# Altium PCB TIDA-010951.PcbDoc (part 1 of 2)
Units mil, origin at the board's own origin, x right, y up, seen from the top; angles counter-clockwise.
Board outline 3346.46 x 3346.46 mil, 2 copper layers (Top Layer, Bottom Layer), stack 62 mil thick; 118 components, 74 nets, 305 pads, 166 vias.
Unrouted connection lines stored in the file: 4.
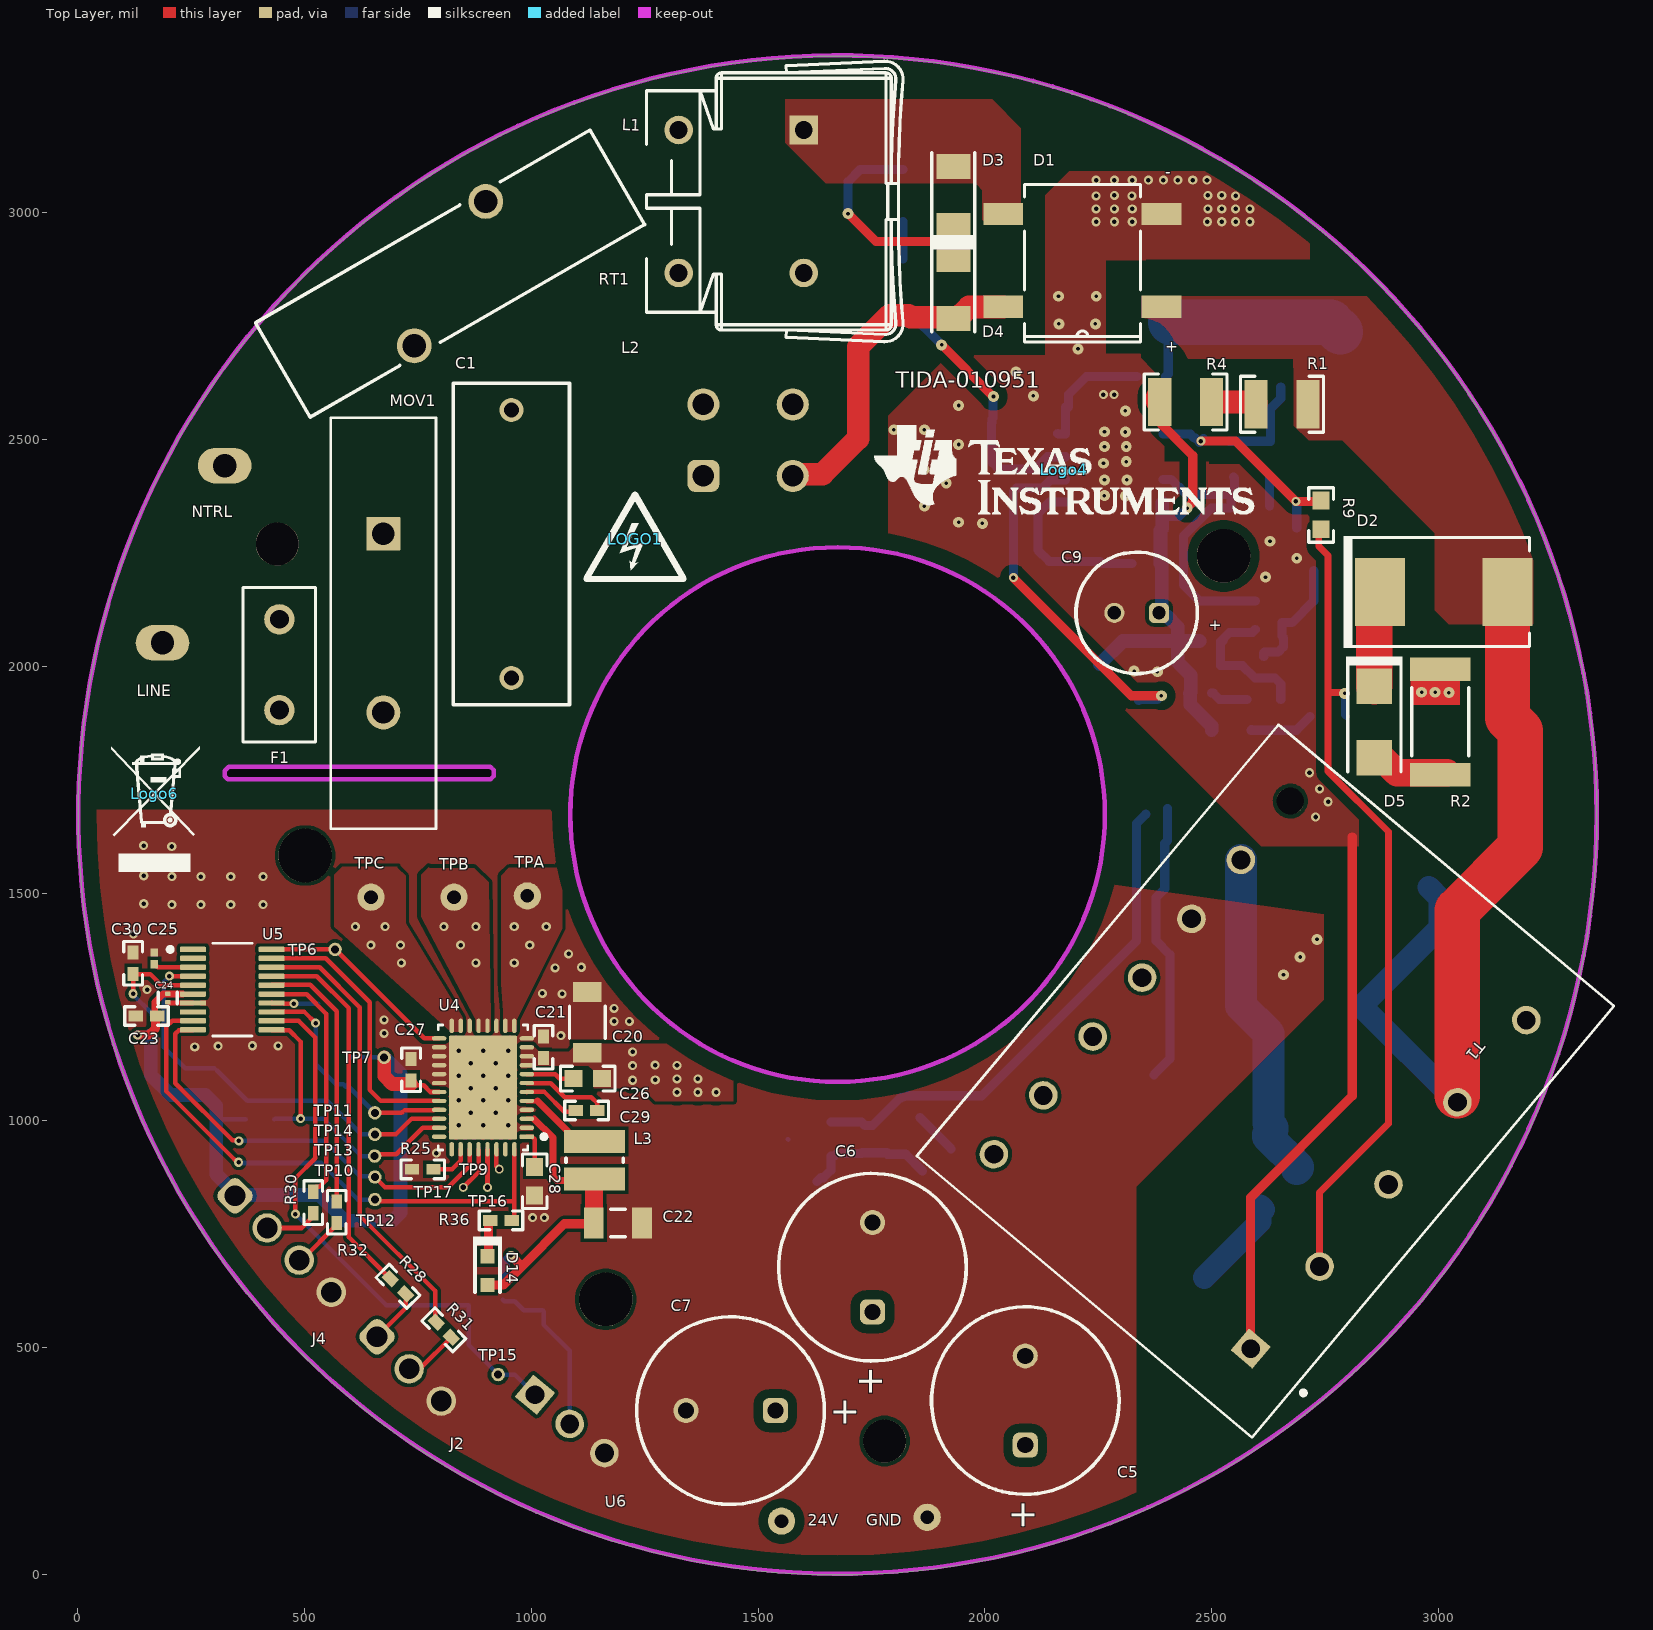
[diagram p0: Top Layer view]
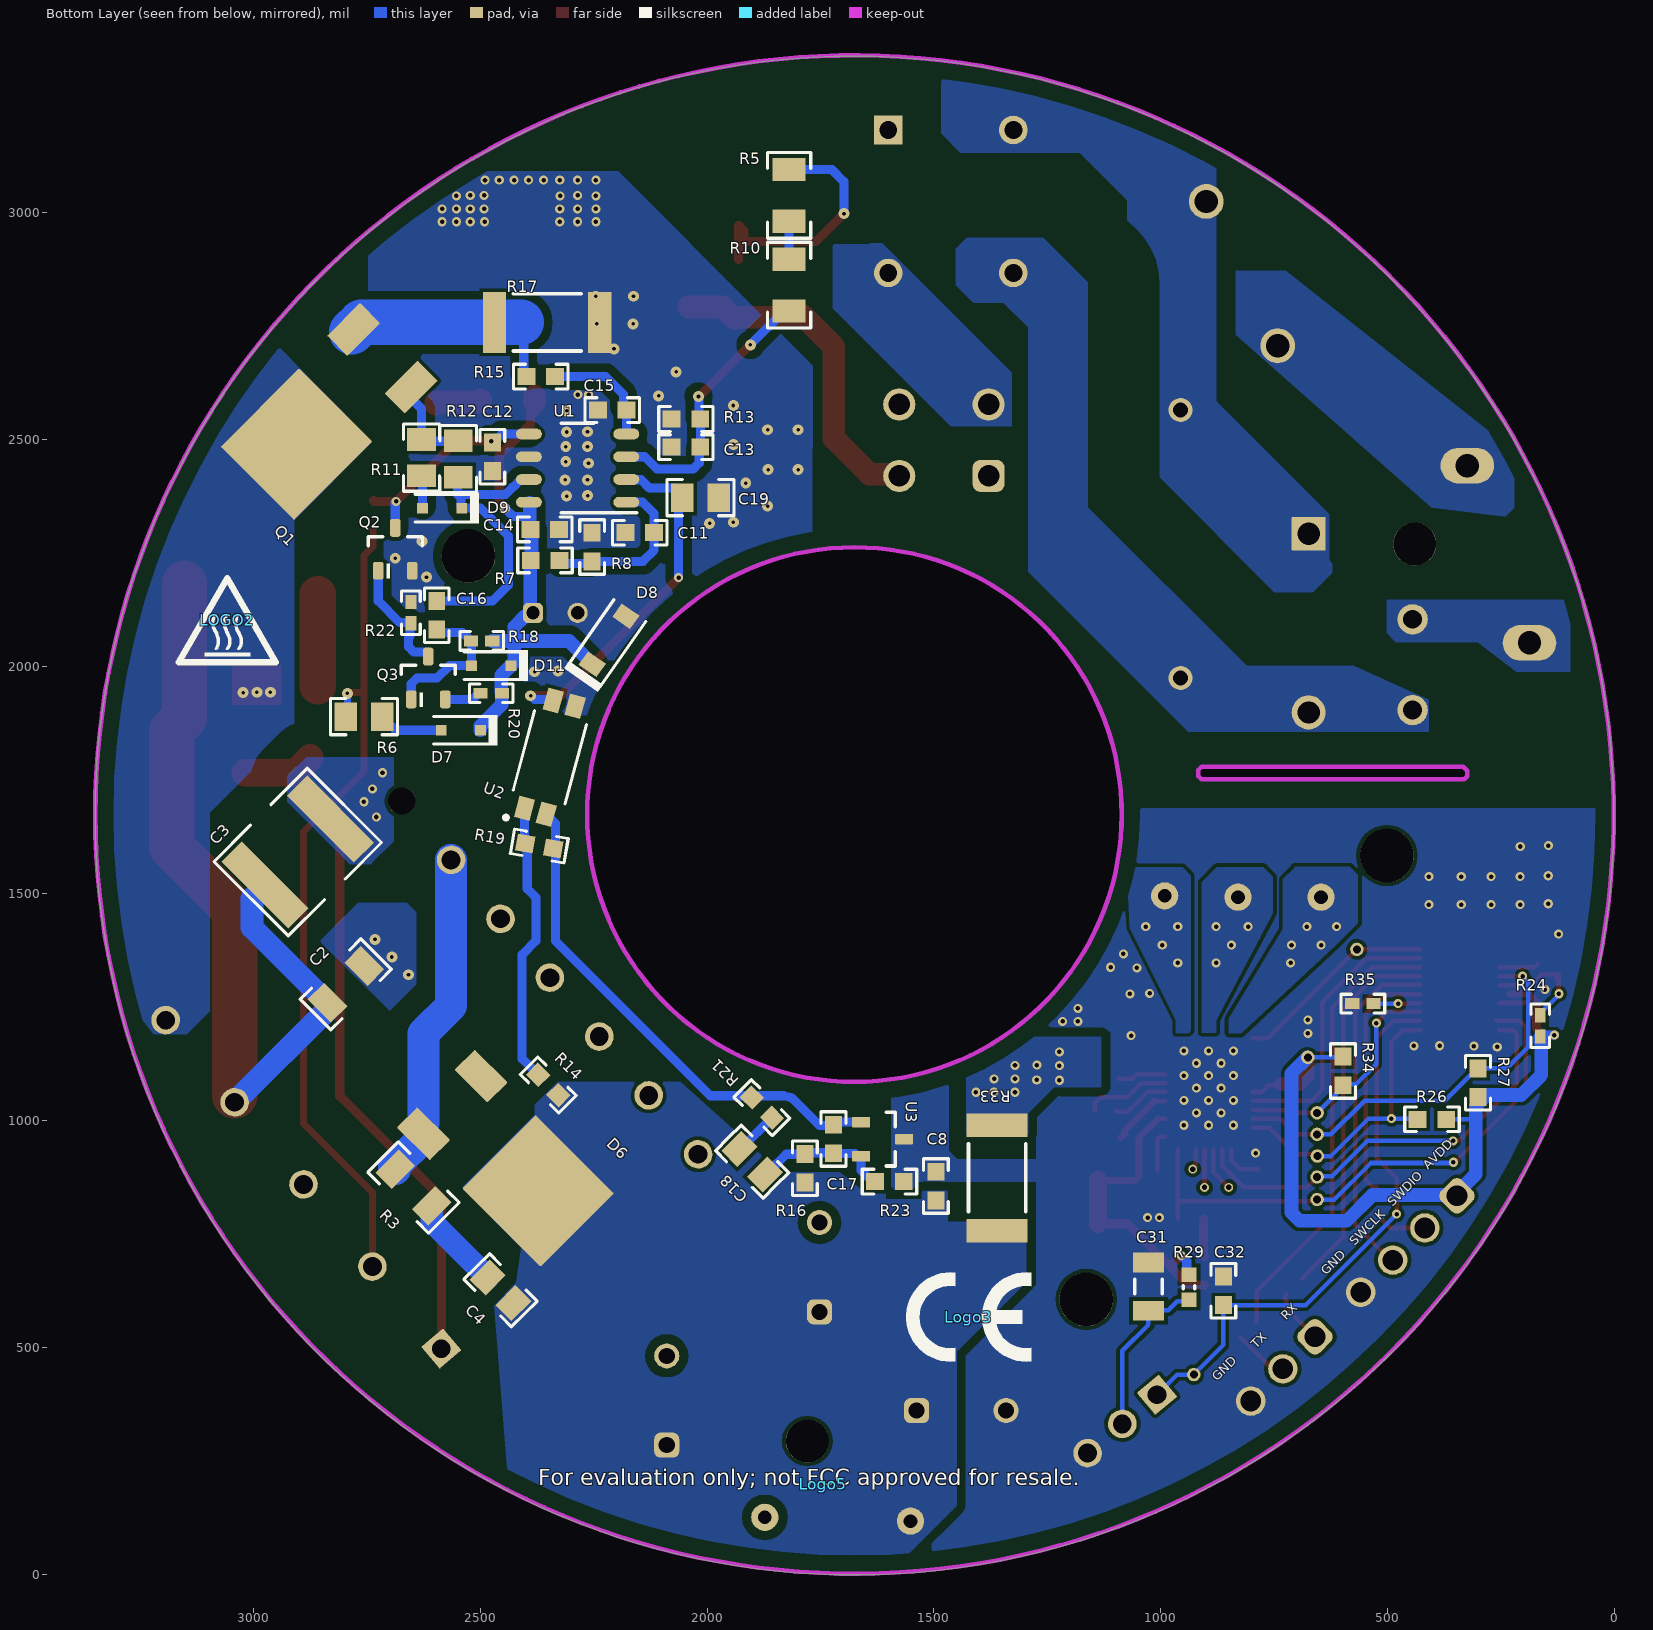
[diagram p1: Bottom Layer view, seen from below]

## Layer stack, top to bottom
Top Solder: solder mask 0.4, Solder Resist, Dk 3.5
Top Layer: signal copper 1.4
Dielectric1: core 59.2, FR-4 High Tg, Dk 4.8
Bottom Layer: signal copper 1.4
Bottom Solder: solder mask 0.4, Solder Resist, Dk 3.5

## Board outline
1675.2,-1.2 cw(c1675.2,1672.03) 1.97,1672.03 cw(c1675.2,1672.03) 1675.2,3345.26 cw(c1675.2,1672.03) 3348.42,1672.03 cw(c1675.2,1672.03)
cut-out: 1675.2,1085.28 cw(c1675.2,1674.21) 1086.26,1674.21 cw(c1675.2,1674.21) 1675.2,2263.15 cw(c1675.2,1674.21) 2264.13,1674.21 cw(c1675.2,1674.21)
cut-out: 333.85,1779.53 910.16,1779.53 917.32,1772.36 917.32,1758.86 910.61,1752.14 331.69,1752.14 324.98,1758.86 324.98,1770.66

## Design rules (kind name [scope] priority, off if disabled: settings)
AcuteAngle [All] p1: minimum=4.50000000000000E+0001 checktracksonly=FALSE
AssemblyTestPointUsage [All] p1: valid=2
BoardOutlineClearance BoardOutlineClearance_MountingHoles [OnCopper and InComponentClass('Mounting Holes')] p1: gap=39.37 ignorepadtopadclearanceinfootprint=FALSE
BoardOutlineClearance BoardOutlineClearance_Poly [OnCopper and IsPoly] p2: gap=25 ignorepadtopadclearanceinfootprint=FALSE
BoardOutlineClearance [OnCopper and Not InComponentClass('Logo') and not InComponentClass('FiducialMark') and not InRegion(1000,500,4000,800) and not InPoly] p3: gap=40 ignorepadtopadclearanceinfootprint=FALSE
Clearance "Clearance_HV AC to PGND" [InNetClass('High Volt AC')or InNetClass('High Volt AC/2') vs InNet('PGND')] p1: gap=10 ignorepadtopadclearanceinfootprint=TRUE
Clearance Clearance_Outline [InPolygon vs OnLayer('Keep-Out Layer')] p2: gap=35.43 ignorepadtopadclearanceinfootprint=TRUE
Clearance "Clearance_HV to All" [InNetClass('High Volt DC')Or InNet('NetQ1_2') vs (InNet('PGND')) And Not InComponent('T1')And Not InComponent('R1')] p3: gap=78.74 ignorepadtopadclearanceinfootprint=TRUE
Clearance "Clearance_HV to LV" [InNetClass('High Volt DC') vs InNetClass('LV')] p4: gap=196.85 ignorepadtopadclearanceinfootprint=TRUE
Clearance "Clearance_HV to To PGND" [InNet('NetC2_2')and not InAnyComponent vs InNet('PGND')] p5: gap=118.11 ignorepadtopadclearanceinfootprint=TRUE
Clearance "Clearance_24V to GND" [InNet('+24V') or ((InNet('NetC20_1')and Not OnTopLayer)or(InNet('NetC4_1'))or (InNet('NetD6_3'))and OnBottomLayer)and Not InAnyComponent vs InNet('GND')] p6: gap=19.68 ignorepadtopadclearanceinfootprint=TRUE
Clearance "Clearance_All to PGND" [Not InAnyComponent vs InNet('PGND')] p7: gap=19.68 ignorepadtopadclearanceinfootprint=TRUE
Clearance "Clearance_High Current to PGND" [InNetClass('Primary Out') or InNet('NetQ1_3')and not InAnyComponent vs InNet('PGND')] p8: gap=118.11 ignorepadtopadclearanceinfootprint=TRUE
Clearance "Clearance_AC L to N" [(InNetClass('High Volt AC L'))And(Not InComponent('D1')) vs (InNetClass('High Volt AC N'))And(Not InComponent('D1'))] p9: gap=157.48 ignorepadtopadclearanceinfootprint=TRUE
Clearance "Clearance_TH Pin to SMD Pad" [IsThruPin And OnMultiLayer And InAnyComponent And Not( InComponent('D6')or InComponent('T1') or InComponent('C9')or InComponent('TP7')) vs InSMTComponent And OnBottomLayer] p10: gap=78.74 ignorepadtopadclearanceinfootprint=FALSE
Clearance Clearance_Keepouts [((IsTrack Or IsArc) And Not InPoly) And IsFree and IsKeepOut vs ((IsTrack Or IsArc) And Not InPoly) And IsFree and IsKeepOut] p11: gap=39.37 ignorepadtopadclearanceinfootprint=FALSE
Clearance Clearance_Poly [InPolygon and not InAnyComponent] p12: gap=8 ignorepadtopadclearanceinfootprint=TRUE
Clearance Clearance_FiducialMark [IsKeepOut and InComponentClass('FiducialMark') vs IsPad and InComponentClass('FiducialMark')] p13: gap=0 ignorepadtopadclearanceinfootprint=FALSE
Clearance [All] p14 off: gap=8 ignorepadtopadclearanceinfootprint=TRUE
ComponentClearance ComponentClearance_MountingHoles_FiducialMarks [InComponentClass('Mounting Holes') vs InComponentClass('FiducialMark')] p1 off: gap=50 collisioncheckmode=3 verticalgap=10 showdistances=FALSE
ComponentClearance ComponentClearance_Shunt [InComponentClass('Header') vs InComponentClass('Shunt')] p2 off: gap=0 collisioncheckmode=3 verticalgap=0 showdistances=FALSE
ComponentClearance ComponentClearance_Logo [InComponentClass('Logo')] p3 off: gap=30 collisioncheckmode=3 verticalgap=10 showdistances=FALSE
ComponentClearance ComponentClearance_ScrewToNut [(HasFootprint('NY PMS 440 0025 PH')) vs (HasFootprint('Keystone_1902C'))] p4 off: gap=5 collisioncheckmode=3 verticalgap=10 showdistances=FALSE
ComponentClearance ComponentClearance_MountingHoles [InComponentClass('Mounting Holes')] p5 off: gap=100 collisioncheckmode=3 verticalgap=100000 showdistances=FALSE
ComponentClearance ComponentClearance_SmallPassives [HasFootprint('0201*') or HasFootprint('0402*') or HasFootprint('0508') or HasFootprint('0603*') or HasFootprint('0612') or HasFootprint('0805*') or HasFootprint('0815*') or HasFootprint('0830*') or HasFootprint('1206*') or HasFootprint('1210*') or HasFootprint('1808*') or HasFootprint('1812*') or HasFootprint('1825*') or HasFootprint('2010*') or HasFootprint('2220*') or HasFootprint('2225*') or HasFootprint('2512*') or HasFootprint('2728*') or HasFootprint('3518*') vs HasFootprint('0201*') or HasFootprint('0402*') or HasFootprint('0508') or HasFootprint('0603*') or HasFootprint('0612') or HasFootprint('0805*') or HasFootprint('0815*') or HasFootprint('0830*') or HasFootprint('1206*') or HasFootprint('1210*') or HasFootprint('1808*') or HasFootprint('1812*') or HasFootprint('1825*') or HasFootprint('2010*') or HasFootprint('2220*') or HasFootprint('2225*') or HasFootprint('2512*') or HasFootprint('2728*') or HasFootprint('3518*')] p6 off: gap=14.96 collisioncheckmode=3 verticalgap=10 showdistances=FALSE
ComponentClearance ComponentClearance_THtoSMT [IsThruComponent vs IsSMTComponent] p7 off: gap=10 collisioncheckmode=3 verticalgap=10 showdistances=FALSE
ComponentClearance ComponentClearance_THtoTH [IsThruComponent vs IsThruComponent] p8 off: gap=10 collisioncheckmode=3 verticalgap=10 showdistances=FALSE
ComponentClearance [All] p9 off: gap=10 collisioncheckmode=3 verticalgap=10 showdistances=FALSE
DiffPairsRouting [All] p1: maxlimit=100 minlimit=10 mostfreqgap=10 toplayer_minwidth=15 toplayer_maxwidth=15 toplayer_prefwidth=15 bottomlayer_minwidth=15 bottomlayer_maxwidth=15 bottomlayer_prefwidth=15 maxuncoupledlength=1000
FabricationTestPointUsage TestPointUsage [All] p1: valid=2 allowmultiple=FALSE
FabricationTestpoint Testpoint [All] p1: side=3 testpointundercomponent=TRUE minsize=40 maxsize=100 preferedsize=60 minholesize=0 maxholesize=40 preferedholesize=32 testpointgrid=1 allowsidetop=TRUE allowsidebottom=TRUE usegrid=TRUE gridtolerance=0.01
FanoutControl Fanout_LCC [IsLCC] p1: bgadir=Out bgaviamode=Centered fanoutstyle=Auto fanoutdirection=Alternating viagrid=1 // Fanout_LCC (Default Rule)
FanoutControl Fanout_BGA [IsBGA] p2: bgadir=Out bgaviamode=Centered fanoutstyle=Auto fanoutdirection=Alternating viagrid=1 // Fanout_BGA (Default Rule)
FanoutControl Fanout_Default [All] p4: bgadir=Out bgaviamode=Centered fanoutstyle=Auto fanoutdirection=Alternating viagrid=1 // Fanout_Default (Default Rule)
FanoutControl Fanout_Small [(CompPinCount < 5)] p5: bgadir=Out bgaviamode=Centered fanoutstyle=Auto fanoutdirection=OutThenIn viagrid=1 // Fanout_Small (Default Rule)
HoleSize [All] p1: absolutevalues=TRUE maxlimit=251 minlimit=7.87 maxpercent=80.000 minpercent=20.000
MinimumSolderMaskSliver MinimumSolderMaskSliver_Logo [InComponentClass('Logo') vs InComponentClass('Logo')] p1: minsoldermaskwidth=0.7
MinimumSolderMaskSliver [All] p2: minsoldermaskwidth=3.94
PlaneConnect [All] p1: planeconnectstyle=Relief reliefexpansion=10 reliefentries=4 reliefconductorwidth=10 reliefairgap=10
PolygonConnect [All] p1: connectstyle=Direct reliefconductorwidth=10 reliefentries=4 polygonreliefangle="90 Angle" airgapwidth=10
RoutingVias ThermalPadVias [IsVia and InAnyComponent] p1: holewidth=7.87 width=19.68 viastyle="Through Hole" minholewidth=7.87 minwidth=19.68 maxholewidth=12.99 maxwidth=23.62
RoutingVias [All] p2: holewidth=16 width=34 viastyle="Through Hole" minholewidth=7.87 minwidth=24 maxholewidth=40 maxwidth=65
SilkToBoardRegionClearance [Not ((IsComment or IsDesignator) And (Hide <> 'False')) and not InRegion(1000,500,4000,800)] p1:
SilkToSilkClearance SilkToSilkClearance_Pb-FreeLogo [(HasFootprint('Pb-Free_Overlay_Medium') OR HasFootprint('Pb-Free_Overlay_Small')) vs (HasFootprint('Pb-Free_Overlay_Medium') OR HasFootprint('Pb-Free_Overlay_Small'))] p1 off: silktosilkclearance=0
SilkToSilkClearance [All] p2 off: silktosilkclearance=3.94
SilkToSolderMaskClearance SilkToComponentPadClearance [(IsPad or IsFill or IsRegion) and InAnycomponent] p1 off: minsilkscreentomaskgap=5 clearancetoexposedcopper=TRUE
SilkToSolderMaskClearance "Silk to Solder Mask Opening" [All] p2 off: minsilkscreentomaskgap=3.94 clearancetoexposedcopper=FALSE
SolderMaskExpansion [All] p1: expansion=1.97 istentingtop=FALSE
UnRoutedNet [All] p1: checkbadconnections=TRUE
Width [All] p1: maxlimit=100 minlimit=6 preferedwidth=10
14 further rules are at their usual default settings.

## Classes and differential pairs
component class Logo: Logo4
net class "High Volt AC": NetD3_1
net class "High Volt AC/2": NetR5_1
net class "High Current Sensing": NetQ1_3
net class "High Volt AC L": LINE NetC1_2 NetD1_3
net class "TL431 Ref": NetC17_2
net class "Primary Out": NetQ1_2
net class "Opto K": NetC17_1
net class "Opto A": NetR14_1
net class "High Volt DC": NetC2_2 NetR1_1
net class "High Volt AC N": NetC1_1 NetD1_4 NetL1_4
net class "Aux 16.5V": NetR6_2
net class "24V DC": +24V
net class "18V VDD": VDD
component class "TIDA-010951_Motor Driver": C20 C21 C22 C23 C24 C25 C26 C27 C28 C29 C30 C31 C32 D14 J2 J4 L3 LOGO1 LOGO2 Logo3 Logo4 Logo5 Logo6 R24 R25 R26 R27 R28 R29 R30 R31 R32 R33 R34 R35 R36 TP6 TP7 TP9 TP10 TP11 TP12 TP13 TP14 TP15 TP16 TP17 TPA TPB TPC U4 U5 U6
component class TIDA-010951_ACDC: 24V +24V C1 C2 C3 C4 C5 C6 C7 C8 C9 C11 C12 C13 C14 C15 C16 C17 C18 C19 D1 D2 D3 D4 D5 D6 D7 D8 D9 D11 F1 GND L1 L2 MOV1 Q1 Q2 Q3 R1 R2 R3 R4 R5 R6 R7 R8 R9 R10 R11 R12 R13 R14 R15 R16 R17 R18 R19 R20 R21 R22 R23 RT1 T1 U1 U2 U3
component class Header: J2 J4

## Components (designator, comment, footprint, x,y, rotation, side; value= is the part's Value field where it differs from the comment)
24V "TP_H0.45P0.75" TP_H045P075#1 1551.72,117.53 r90 top
C1 "450MPK474J" MPK_1800x650 956.69,2270.28 r90 top value=0.47uF
C2 "GRM31BR73A222KW01L" 1206 2795.86,1300.23 r315 bottom value=2200pF
C3 "GRM55DR73A104KW01L" 2220 2901.74,1591.58 r135 bottom value=0.1uF
C4 "DNP" 0805_HV 2455.01,626.12 r225 bottom
C5 "1000uF" WCAP-ATLL_D10H30 2088.76,383.17 r270 top
C6 "1000uF" WCAP-ATLL_D10H30 1752.12,676.93 r270 top
C7 "1000uF" WCAP-ATLL_D10H30 1439.61,361.01 r0 top
C8 "UMK107AB7105KA-T" 0603 1495.67,855.78 r90 bottom value=1uF
C9 "UVR2A220MED1TD" VR_630X1100 2334.22,2118.53 r180 top value=22uF
C11 "C1608X7R1H103K080AA" 0603 2148.2,2295.14 r0 bottom value=0.01uF
C12 "GRM1885C1H100JA01D" 0603 2472.85,2462.57 r90 bottom value=10pF
C13 "C0603X102K5RACTU" 0603 2046.52,2483.65 r0 bottom value=1000pF
C14 "GRM188R71H104KA93D" 0603 2357.71,2302.39 r180 bottom value=0.1uF
C15 "C1608C0G1H101J080AE" 0603 2208.87,2565.24 r0 bottom value=100pF
C16 "GRM1885C1H100JA01D" 0603 2595.49,2113.6 r90 bottom value=10pF
C17 "C1608X5R1V225K080AC" 0603 1721.4,959.4 r270 bottom value=2.2uF
C18 "C2012X7R1V475K125AC" 0805_HV 1900.57,909.42 r45 bottom value=4.7uF
C19 "C2012X6S1H225K125AB" 0805_HV 2014.31,2372.54 r180 bottom value=2.2uF
C20 "UMK316BBJ106KL-T" 1206_190 1124.02,1216.4 r90 top value=10uF
C21 "C1005X7R1H104K050BB" 0402 1027.28,1161.47 r90 top value=0.1uF
C22 "GRM31CR71A226KE15L" 1206_180L 1191.31,774.39 r0 top value=22uF
C23 "GRM155R60J106ME11" 0402 152.56,1230.31 r180 top value=10uF
C24 "GRM033R60J104KE19D" FP-GRM033R60J104KE19D_0201-MFG 199.62,1269.85 r90 top
C25 "GRM033R60J474KE90D" 0201_033 170.06,1357.43 r270 top value=0.47uF
C26 "GRM188R71C105KE15D" 0603 1125,1092.52 r180 top value=1uF
C27 "GRM155R60J105KE19D" 0402 735.64,1111.89 r90 top value=1uF
C28 "LMK107BJ225KA-T" 0603 1007.97,866.38 r270 top value=2.2uF
C29 "C1005X7R1H473K050BB" 0402 1122.24,1022.16 r0 top value=0.047uF
C30 "GCM155R71H102KA37D" 0402 123.03,1346.46 r90 top value=1000pF
C31 "GRM31CR71A226KE15L" 1206_180L 1027.28,634.04 r90 bottom value=22uF
C32 "885012006012" 0603 862.2,625 r90 bottom value=470pF
D1 "DF1506S-T" DF-S 2214.79,2895.14 r180 top value=600V
D2 "SMCJ150A-TP" SMC 3010.83,2164.37 r0 top value=150V
D3 "CGRM4005-G" MINI-SMA 1930.37,3037.4 r90 top value=600V
D4 "CGRM4005-G" MINI-SMA 1930.37,2832.5 r270 top value=600V
D5 "MURA160T3G" SMA 2857.95,1878.21 r270 top value=600V
D6 "STTH802B-TR" DPAK 2466.69,939.81 r225 bottom value=200V
D7 "BAS20HT1G" SOD-323 2542.56,1860.04 r0 bottom
D8 "MMSZ4705-E3-08" SOD-123 2215.91,2058.45 r125 bottom value=18V
D9 "BAS20HT1G" SOD-323 2583.66,2349.29 r0 bottom
D11 "BAS20HT1G" SOD-323 2475.44,2002.38 r0 bottom
D14 "150060RS75000" WL-SMCW_RED 903.9,669.26 r270 top value=Red
F1 "39213150000" FUSE_392 445.41,2004.33 r90 top value=3.15A
GND "TP_H0.45P0.75" TP_H045P075#1 1872.65,125.84 r90 top
J2 "61300311121" WURTH_61300311121 731.22,452.83 r315 top
J4 "61300411121" WURTH_61300411121 453.74,727.95 r315 top
L1 "744861018" WE-TFCH_UT 1462.96,3025 r270 top value=1.8mH
L2 "7447231102" WE-TIF_1018 1477.98,2499.04 r0 top value=1mH
L3 "78438335470" WE-MAIA_3015 1139.95,912.69 r270 top value=47uH
LOGO1 "DANGER HIGH VOLTAGE" IEC_HighVoltage_Small 1228.93,2281.31 r0 top
LOGO2 "CAUTION HOT SURFACE" IEC_HotSurface_Small 3056.94,2102.44 r180 bottom
Logo3 "CE Mark" CE_Mark_5mm 1423.87,567.11 r180 bottom
Logo4 "Texas Instruments" TI_Stacked_Overlay_Small 2174.42,2433.74 r0 top
Logo5 "FCC disclaimer" FCC_disclaimer 1744.47,198.63 r180 bottom
Logo6 "WEEE logo" WEEE_Minimum 170.7,1720.42 r0 top
MOV1 "MOV-20D471K" FP-MOV-20D471K_RADIAL-MFG 674.5,2096.03 r270 top
Q1 "IPD70R360P7SAUMA1" DPAK 2809.88,2584.81 r315 bottom value=700V
Q2 "MMBT3904-7-F" SOT-23 2686.96,2258.56 r90 bottom value="40 V"
Q3 "MMBT3906-7-F" SOT-23 2614.19,1975.18 r90 bottom value="40 V"
R1 "RC1210JR-07200KL" 1210 2654.48,2578.25 r0 top value=200k
R2 "CRCW251222R0JNEGHP" 2512 3003.28,1878.21 r270 top value=22
R3 "CRCW120647R0JNEA" 1206 2646.78,852.6 r225 bottom value=47
R4 "RC1210JR-07200KL" 1210 2442.14,2583.29 r0 top value=200k
R5 "RC1206FR-07510KL" 1206 1818.98,3038.39 r90 bottom value=510k
R6 "RC0805JR-073R3L" 0805_HV 2755.86,1889.97 r0 bottom value=3.3
R7 "RC0603FR-07301KL" 0603 2356.87,2234.32 r0 bottom value=301k
R8 "RC0603FR-0730K1L" 0603 2253.26,2263.65 r270 bottom value=30.1k
R9 "RC0603FR-0747KL" 0603 2740.63,2334.35 r270 top value=47.0k
R10 "RC1206FR-07510KL" 1206 1818.98,2840.76 r90 bottom value=510k
R11 "RC0805JR-072R2L" 0805_HV 2629.09,2460.52 r90 bottom value=2.2
R12 "RPC0805JT4R70" 0805_HV 2548.03,2457.57 r90 bottom value=4.7
R13 "RC0603FR-076K8L" 0603 2046.52,2545.66 r180 bottom value=6.80k
R14 "CR0603-JW-472GLF" 0603 2349.77,1078.32 r225 bottom value=4.7k
R15 "RC0603JR-071KL" 0603 2366.58,2639.12 r180 bottom value=1.0k
R16 "RC0603FR-07412KL" 0603 1784.34,895.17 r270 bottom value=412k
R17 "ERJ-1TRQJR68U" 2512 2352.36,2758.54 r0 bottom value=0.68
R18 "ERJ-2RKF1002X" 0402 2496.52,2056.7 r0 bottom value=10.0k
R19 "RC0603JR-071KL" 0603 2369.57,1604.94 r10 bottom value=1.0k
R20 "ERJ-2GEJ203X" 0402 2475.44,1941.58 r0 bottom value=20k
R21 "RC0603FR-0718KL" 0603 1879.19,1028.57 r225 bottom value=18.0k
R22 "RC0402FR-074K99L" 0402 2652.45,2119.09 r270 bottom value=4.99k
R23 "RC0603FR-0747K5L" 0603 1598.1,865.38 r0 bottom value=47.5k
R24 "RC0402FR-0747KL" 0402 164.37,1208.66 r270 bottom value=47.0k
R25 "CRCW040210K0JNED" 0402 761.42,892.48 r180 top value=10k
R26 "RC0603FR-075K1L" 0603 402.76,1002.77 r180 bottom value=5.10k
R27 "RC0603FR-075K1L" 0603 301.42,1083.53 r270 bottom value=5.10k
R28 "CRCW0402180RJNED" 0402 706.69,634.84 r315 top value=180
R29 "CRCW06035K10JNEA" 0603L 937.99,632.87 r90 bottom value=5.1k
R30 "CRCW0402180RJNED" 0402 520.16,819.32 r270 top value=180
R31 "CRCW0402180RJNED" 0402 807.83,539.04 r315 top value=180
R32 "CRCW0402180RJNED" 0402 572.04,798.01 r270 top value=180
R33 "CRCW25120000Z0EGHP" 2512 1360.87,873.49 r90 bottom value=0
R34 "RC0603FR-075K1L" 0603 598.74,1109.29 r90 bottom value=5.10k
R35 "CRCW040210K0JNED" 0402 555.01,1257.77 r0 bottom value=10k
R36 "ERA2AED102X" 0402 933.8,780 r180 top value=1.00k
RT1 "SCK205R0MSBY502" SCK20_S 821.35,2865.94 r120 top value=5
T1 "G084231" FP-G084231_PTH_TRANSFORMER_31MM50_24MM50-MFG 2617.63,1087.09 r140 top locked
TP6 "TP_H0.45P0.75" TP_H045P075#2 568.19,1377.12 r140 top
TP7 "TP_H0.45P0.75" TP_H045P075#2 676.21,1139.19 r180 top
TP9 "TP_H0.45P0.75" TP_H045P075#3 929.82,892.96 r180 top
TP10 "TP_H0.45P0.75" TP_H045P075#2 655.8,875.67 r250 top
TP11 "TP_H0.45P0.75" TP_H045P075#2 655.8,1017.06 r180 top
TP12 "TP_H0.45P0.75" TP_H045P075#2 655.8,826.04 r180 top
TP13 "TP_H0.45P0.75" TP_H045P075#2 655.32,921.81 r180 top
TP14 "TP_H0.45P0.75" TP_H045P075#2 655.8,969.55 r180 top
TP15 "TP_H0.45P0.75" TP_H045P075#2 927.54,440.4 r270 top
TP16 "TP_H0.45P0.75" TP_H045P075#3 903.94,852.73 r45 top
TP17 "TP_H0.45P0.75" TP_H045P075#3 850.61,852.73 r45 top
TPA "TP_H0.45P0.75" TP_H045P075#1 991.77,1495.06 r90 top
TPB "TP_H0.45P0.75" TP_H045P075#1 830.14,1492.22 r90 top
TPC "TP_H0.45P0.75" TP_H045P075#1 647.19,1492.22 r90 top
U1 "UCC28810DR" D0008A_N 2285.14,2437.57 r0 bottom
U2 "VOS617A-7X001T" SSOP-4_VISHAY 2346.48,1800.19 r105 bottom
U3 "ATL431AIDBZR" DBZ0003A_N 1613.16,958.99 r180 bottom
U4 "MCF8315A1VRGFR" RGF0040E-IPC_B 894.06,1072.77 r180 top
U5 "MSPM0L1306SDGS20" DGS0020A-MFG 341.65,1288.53 r0 top
U6 "TSOP32238" FP-TSOP32238_SIP3-MFG 1053.36,293.94 r230 top

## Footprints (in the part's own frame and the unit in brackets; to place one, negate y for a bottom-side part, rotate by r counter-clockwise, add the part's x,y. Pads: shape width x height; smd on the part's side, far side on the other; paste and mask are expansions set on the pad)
0201_033 [mm] "SMD, 2-Leads, Height 0.33mm"
  rect 0.46x0.42 smd mask+0.048: 1(-0.33,0) 2(0.33,0)
  body extent -0.31,-0.16 0.31,0.16, height 0.33
0402 [mm] "0402 from SM-752 data"
  rect 0.8x0.6 smd: 1(-0.6,0) 2(0.6,0)
  silkscreen extent -1.22,-0.52 1.22,0.52, body extent -0.55,-0.3 0.55,0.3, height 0.6
0603 [mm] "0603 from SM-752 data"
  rect 1x0.95 smd: 1(-0.8,0) 2(0.8,0)
  silkscreen extent -1.52,-0.69 1.52,0.69, body extent -0.87,-0.47 0.87,0.47, height 1
0603L [mm] "0603 from SM-752 data"
  rect 0.8x0.85 smd: 1(-0.7,0) 2(0.7,0)
  silkscreen extent -0.07,-0.33 0.07,0.33, body extent -0.87,-0.47 0.87,0.47, height 1
0805_HV [mil] "0805 with 30mil clearance between pads"
  rect 50x63 smd: 1(-40,0) 2(40,0)
  silkscreen extent -74,-40 74,40, body extent -43,-29 43,29, height 57
1206 [mm] "1206 from SM-752 data"
  rect 1.3x1.85 smd: 1(-1.45,0) 2(1.45,0)
  silkscreen extent -2.4,-1.21 2.4,1.21, body extent -1.7,-0.9 1.7,0.9, height 1.35
1206_180L [mm] "1206_180"
  rect 1.1x1.75 smd: 1(-1.35,0) 2(1.35,0)
  silkscreen extent -0.4,-0.77 0.4,0.77, body extent -1.75,-0.95 1.75,0.95, height 1.8
1206_190 [mm] "1206_190"
  rect 1.1x1.6 smd: 1(-1.7,0) 2(1.7,0)
  silkscreen extent -0.9,-1 0.9,1, body extent -1.75,-0.95 1.75,0.95, height 1.9
1210 [mm] "1210 from SM-752 data"
  rect 1.3x2.7 smd: 1(-1.45,0) 2(1.45,0)
  silkscreen extent -2.32,-1.57 2.32,1.57, body extent -1.7,-1.35 1.7,1.35, height 1.35
2220 [mm] "Chip Capacitor, Body 5.7x5.0mm, IPC Medium Density"
  rect 1.6x5.3 smd: 1(-2.6,0) 2(2.6,0)
  silkscreen extent -3.69,-2.94 3.69,2.94, body extent -2.95,-2.62 2.95,2.62, height 1.35
2512 [mm] "Chip Resistor, Body 6.3x3.2mm, IPC Medium Density"
  rect 1.3x3.4 smd: 1(-2.95,0) 2(2.95,0)
  silkscreen extent -1.9,-1.6 1.9,1.6, body extent -3.22,-1.67 3.22,1.67, height 0.71
CE_Mark_5mm [mil] "Minimum text height for CE Mark"
  silkscreen extent -138,-98 138,98
D0008A_N [mm] "SOIC, 8-Leads, Body 4.9x3.9mm, Pitch 1.27mm, IPC Medium Density"
  oval 1.45x0.6 smd: 1(-2.725,1.905) 2(-2.725,0.635) 3(-2.725,-0.635) 4(-2.725,-1.905) 5(2.725,-1.905) 6(2.725,-0.635) 7(2.725,0.635) 8(2.725,1.905)
  silkscreen extent -3.3,-2.5 0.9,2.5, body extent -3,-2.45 3,2.45, height 1.63
DBZ0003A_N [mm] "SOT23, 3-Leads, Body 2.9x1.3mm, Pitch 0.95mm, Lead Span 2.4mm, IPC Medium Density"
  rrect17% 1x0.6 smd: 1(-1.2,0.95) 2(-1.2,-0.95) 3(1.2,0)
  silkscreen extent 0.2,-1.5 0.7,1.5, body extent -1.26,-1.46 1.26,1.46, height 0.98
DF-S [mil] "Diodes Inc. recommended land pattern per ap02001.pdf rev 30"
  rect 88x49 smd: 1(-174.5,102.36) 2(-174.5,-102.36) 3(174.5,-102.36) 4(174.5,102.36)
  silkscreen extent -128,-168 128,180, body extent -205,-168 205,168, height 108
DGS0020A-MFG [mm]
  rrect33% 1.45x0.3 smd paste+0 mask+0: 1(-2.2,2.25) 2(-2.2,1.75) 3(-2.2,1.25) 4(-2.2,0.75) 5(-2.2,0.25) 6(-2.2,-0.25) 7(-2.2,-0.75) 8(-2.2,-1.25) 9(-2.2,-1.75) 10(-2.2,-2.25) 11(2.2,-2.25) 12(2.2,-1.75) 13(2.2,-1.25) 14(2.2,-0.75) 15(2.2,-0.25) 16(2.2,0.25) 17(2.2,0.75) 18(2.2,1.25) 19(2.2,1.75) 20(2.2,2.25)
  silkscreen extent -3.6,-2.6 1.1,2.6, body extent -2.45,-2.55 2.45,2.55, height 1.1
DPAK [mm] "D-PAK, 3-Pads, Body 6.22x6.73mm (max), TO-252AA using nominal STEP model"
  rrect6% 2.6x1.6 smd: 1(-3.4,2.28) 3(-3.4,-2.28)
  rrect2% 6.2x5.8 smd paste-3: 2(3.4,0)
  body extent -3.86,-3.29 5.84,3.29, height 2.48
FCC_disclaimer [mil]
FP-G084231_PTH_TRANSFORMER_31MM50_24MM50-MFG [mm]
  rrect6% 1.6x1.6 hole 1.05 paste-1000 mask+0: 1(-9,12)
  round 1.6 hole 1.05 paste-1000 mask+0: 2(-9,6) 3(-9,0) 4(-9,-6) 5(-9,-12) 7(9,-8.6) 8(9,-4.3) 9(9,0) 10(9,4.3) 11(9,8.6) 12(9,12.9)
  oval 1.524x1.27 hole 1.524 paste-1000 mask+0: 6(9,-12.9)
  silkscreen extent -12.97,-15.75 12.25,15.75, body extent -12.35,-15.85 12.35,15.85, height 0.25
FP-GRM033R60J104KE19D_0201-MFG [mm]
  rrect40% 0.25x0.3 smd paste+0 mask+0: 1(-0.238,0) 2(0.238,0)
  silkscreen extent -0.31,-0.53 0.32,0.53, body extent -0.3,-0.15 0.3,0.15, height 0.33
FP-MOV-20D471K_RADIAL-MFG [mm]
  rrect5% 1.9x1.9 hole 1.25 paste-1000 mask+0: 1(-5,0)
  round 1.9 hole 1.25 paste-1000 mask+0: 2(5,0)
  silkscreen extent -11.5,-2.95 11.5,2.95, body extent -11.6,-3.05 11.6,3.05, height 0.25
FP-TSOP32238_SIP3-MFG [mm]
  rrect6% 1.6x1.6 hole 1.05 paste-1000 mask+0: 1(-1.25,-2.54)
  round 1.6 hole 1.05 paste-1000 mask+0: 2(-1.25,0) 3(-1.25,2.54)
  body extent -3,-3.44 3,3.44, height 0.25
FUSE_392 [mm] "LITTELFUSE"
  round 1.7 hole 1.05: 1(-2.54,0) 2(2.54,0)
  silkscreen extent -4.32,-2.03 4.32,2.03, body extent -4.25,-2 4.25,2, height 8
IEC_HighVoltage_Small [mil]
  silkscreen extent -107,-88 107,97
IEC_HotSurface_Small [mil]
  silkscreen extent -107,-93 107,92
MINI-SMA [mm] "COMCHIP"
  rect 1.4x1.9 smd: 1(-1.65,0) 2(1.65,0)
  silkscreen extent -3,-1.3 2.4,1.3, body extent -1.95,-0.9 1.95,0.9, height 1.7
MPK_1800x650 [mm] "TH, 2-Leads, Body 18x6.5mm, Lead Spacing 15mm"
  round 1.35 hole 0.85: 1(-7.5,0) 2(7.5,0)
  silkscreen extent -9,-3.25 9,3.25, body extent -9,-3.25 9,3.25, height 12
RGF0040E-IPC_B [mm]
  rrect41% 0.806x0.242 smd paste+0 mask+0: 1(-2.453,2.75)
  rrect100% 0.806x0.242 smd paste+0 mask+0: 2(-2.453,2.25) 3(-2.453,1.75) 4(-2.453,1.25) 5(-2.453,0.75) 6(-2.453,0.25) 7(-2.453,-0.25) 8(-2.453,-0.75) 9(-2.453,-1.25) 10(-2.453,-1.75) 11(-2.453,-2.25) 12(-2.453,-2.75) 21(2.453,-2.75) 22(2.453,-2.25) 23(2.453,-1.75) 24(2.453,-1.25) 25(2.453,-0.75) 26(2.453,-0.25) 27(2.453,0.25) 28(2.453,0.75) 29(2.453,1.25) 30(2.453,1.75) 31(2.453,2.25) 32(2.453,2.75)
  rrect100% 0.242x0.806 smd paste+0 mask+0: 13(-1.75,-3.453) 14(-1.25,-3.453) 15(-0.75,-3.453) 16(-0.25,-3.453) 17(0.25,-3.453) 18(0.75,-3.453) 19(1.25,-3.453) 20(1.75,-3.453) 33(1.75,3.453) 34(1.25,3.453) 35(0.75,3.453) 36(0.25,3.453) 37(-0.25,3.453) 38(-0.75,3.453) 39(-1.25,3.453) 40(-1.75,3.453)
  rrect3% 3.8x5.8 smd paste-1000 mask+0: 41(0,0)
  silkscreen extent -3.53,-3.5 2.5,3.5, body extent -2.5,-3.5 2.5,3.5, height 1
SCK20_S [mm] "TH, 2-Leads, Dia 20mm, Pin Spacing 7.5mm"
  round 1.95 hole 1.3: 1(-2.5,3.75) 2(2.5,-3.75)
  silkscreen extent -3.06,-10.8 3.06,10.8, body extent -3,-10.75 3,10.75, height 24.5
SMA [mm] "Molded Diode, 2-Leads, Body 4.3x2.6mm, IPC Medium Density, based on OnSemi component dimensions and land pattern"
  rect 2x2 smd: 1(-2,0) 2(2,0)
  silkscreen extent -3.66,-1.57 2.79,1.57, body extent -2.6,-1.3 2.6,1.3, height 2.42
SMC [mil] "Molded Diode, 2-Leads, Body 6.9x5.8mm, IPC Medium Density, based on OnSemi component dimensions and land patterns"
  rect 110x150 smd: 1(-140.49,0) 2(140.49,0)
  silkscreen extent -221,-123 189,124, body extent -156,-116 156,116, height 91
SOD-123 [mm] "On Semi recommended land pattern"
  rect 0.915x1.22 smd: 1(-1.638,0) 2(1.637,0)
  silkscreen extent -2.74,-1.17 2.03,1.17, body extent -1.93,-0.9 1.93,0.9, height 1.35
SOD-323 [mm] "NXP recommended land pattern"
  rect 0.6x0.6 smd paste-0.05: 1(-1.1,0) 2(1.1,0)
  silkscreen extent -2.06,-0.86 1.53,0.86, body extent -1.3,-0.67 1.3,0.68, height 1.1
SOT-23 [mm] "SOT23, 3-Leads, Body 2.9x1.3mm, Pitch 0.95mm, Lead Span 2.5mm, IPC Medium Density"
  rrect50% 1x0.6 smd: 1(-1.2,0.95) 2(-1.2,-0.95) 3(1.2,0)
  silkscreen extent -1.63,-1.5 0.7,1.5, body extent -1.16,-1.45 1.21,1.45, height 1
SSOP-4_VISHAY [mm] "Vishay Recommened"
  rect 1.25x0.9 smd: 1(-3.125,0.635) 2(-3.125,-0.635) 3(3.125,-0.635) 4(3.125,0.635)
  silkscreen extent -3.98,-1.5 2.3,1.59, body extent -3.5,-1.45 3.5,1.45, height 2.42
TI_Stacked_Overlay_Small [mil]
  silkscreen extent -418,-98 418,98
TP_H045P075#1 [mil] "TP_H0.45P0.75"
  round 60 hole 30: 1(0,0)
TP_H045P075#2 [mil] "TP_H0.45P0.75"
  round 29.53 hole 17.72: 1(0,0)
TP_H045P075#3 [mil] "TP_H0.45P0.75"
  round 19.68 hole 11.81: 1(0,0)
VR_630X1100 [mm] "TH, 2-Leads, Dia 6.3mm, Pin Spacing 2.5mm"
  rrect50% 1.125x1.125 hole 0.75: 1(-1.25,0)
  round 1.125 hole 0.75: 2(1.25,0)
  silkscreen extent -3.4,-3.4 3.4,3.4, body extent -3.4,-3.4 3.41,3.4, height 12.51
WCAP-ATLL_D10H30 [mm] "Aluminum Electrolytic Capacitors, 10x30mm"
  rrect50% 1.4x1.4 hole 0.9: 1(2.5,0)
  round 1.4 hole 0.9: 2(-2.5,0)
  silkscreen extent -5.25,-5.25 5.25,5.25, body extent -4.99,-5 5,5, height 30.31
WE-MAIA_3015 [mm] "SMD, 2-Leads, Body 3x3mm"
  rect 1.3x3.4 smd: 1(-1.05,0) 2(1.05,0)
  silkscreen extent -0.1,-1.6 0.1,1.6, body extent -1.6,-1.6 1.6,1.6, height 1.5
WE-TFCH_UT [mm] "Wurth"
  rect 1.6x1.6 hole 1: 1(-4,3.499)
  round 1.6 hole 1: 2(-4,-3.501) 3(4,-3.501) 4(4,3.499)
  silkscreen extent -7.85,-5.3 7.85,9.05, body extent -7.85,-5.3 7.85,9.05, height 12.02
WE-TIF_1018 [mm] "TH, 4-Leads, Dia 11mm, Pitch 5mm"
  rrect50% 1.8x1.8 hole 1.2: 1(-2.5,-2)
  round 1.8 hole 1.2: 2(2.5,-2) 3(-2.5,2) 4(2.5,2)
  body extent -5.4,-5.4 5.4,5.4, height 18
WEEE_Minimum [mil] "WEEElie bin"
  silkscreen extent -95,-172 99,104
WL-SMCW_RED [mm] "WURTH"
  rect 0.8x0.8 smd: 1(-0.8,0) 2(0.8,0)
  silkscreen extent -1.9,-0.8 1.2,0.8, body extent -0.85,-0.45 0.85,0.45, height 0.8
WURTH_61300311121 [mm] "Header, 2.54mm, 3x1, TH"
  rrect50% 1.65x1.65 hole 1.15: 1(-2.54,0)
  round 1.65 hole 1.15: 2(0,0) 3(2.54,0)
  body extent -3.81,-1.27 3.81,1.27, height 8.54
WURTH_61300411121 [mm] "Header, 2.54mm, 4x1, TH"
  rrect50% 1.65x1.65 hole 1.15: 1(-3.81,0)
  round 1.65 hole 1.15: 2(-1.27,0) 3(1.27,0) 4(3.81,0)
  body extent -5.08,-1.27 5.08,1.27, height 8.54

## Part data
24V GND TP6 TP7 TP9 TP10 TP11 TP12 TP13 TP14 TP15 TP16 TP17 TPA TPB TPC: library part CMP-0003719-1, "Testpoint", Manufacturer="Texas Instruments"
C1: library part CMP-0012309-3, "CAP, Film, 0.47 uF, 450 V, +/- 5%, TH", Cap_Case=18x6.5mm, Manufacturer=Rubycon, Supplier Part Number 1=1189-1824-ND, Tolerance_%=5%, Value1=Unknown, Value2=450V, ValueDisplayed=0.47uF
C2: library part CMP-0008918-2, "CAP, CERM, 2200 pF, 1000 V, +/- 10%, X7R, 1206", Cap_Case=1206, Manufacturer=MuRata, Supplier Part Number 1=490-3496-1-ND, TempCo=X7R, Tolerance_%=10%, Value1=Unknown, Value2=1000V, ValueDisplayed=2200pF
C3: library part CMP-0009470-2, "CAP, CERM, 0.1 uF, 1000 V, +/- 10%, X7R, 2220", Cap_Case=2220, Manufacturer=MuRata, Supplier Part Number 1=490-3505-1-ND, TempCo=X7R, Tolerance_%=10%, Value1=Unknown, Value2=1000V, ValueDisplayed=0.1uF
C4: library part CMP-0008310-1, Cap_Case=0805, TempCo=X5R, Tolerance_%=10%, Value1=Unknown, Value2=250V
C5: library part CMP-03913-55434168-1, "860160575031 WCAP-ATLL Aluminum Electrolytic Capacitors 35VDC", Capacitance=1mF, Case/Package=Radial, Leakage Current=350µA, Max Operating Temperature=105°C, Min Operating Temperature=-55°C, Ripple Current=2.136A, Tolerance=20%, Voltage Rating=35V
C6 C7: library part CMP-03913-55434168-1, "860160575031 WCAP-ATLL Aluminum Electrolytic Capacitors", Capacitance=1mF, Case/Package=Radial, Leakage Current=350µA, Max Operating Temperature=105°C, Min Operating Temperature=-55°C, Ripple Current=2.136A, Tolerance=20%, Voltage Rating=35V
C8: library part CMP-0007508-5, "CAP, CERM, 1 uF, 50 V, +/- 10%, X7R, 0603", Cap_Case=0603, Manufacturer="Taiyo Yuden", Supplier Part Number 1=587-3247-1-ND, TempCo=X7R, Tolerance_%=10%, Value1=Unknown, Value2=50V, ValueDisplayed=1uF
C9: library part CMP-0860355-1, "CAP, AL, 22 µF, 100 V, +/- 20%, TH", Cap_Case=6.3x11mm, Manufacturer=Nichicon, Tolerance_%=20%, Value2=100V, ValueDisplayed=22µF
C11: library part CMP-0007043-2, "CAP, CERM, 0.01 uF, 50 V, +/- 10%, X7R, 0603", Cap_Case=0603, Manufacturer=TDK, Supplier Part Number 1=445-1311-1-ND, TempCo=X7R, Tolerance_%=10%, Value1="0.0539 ohm", Value2=50V, ValueDisplayed=0.01uF
C12: library part CMP-0007170-4, "CAP, CERM, 10 pF, 50 V, +/- 5%, C0G/NP0, 0603", Cap_Case=0603, Manufacturer=MuRata, Supplier Part Number 1=490-1403-1-ND, TempCo=C0G/NP0, Tolerance_%=5%, Value1=Unknown, Value2=50V, ValueDisplayed=100pf
C13: library part CMP-0006976-5, "CAP, CERM, 1000 pF, 50 V, +/- 10%, X7R, 0603", Cap_Case=0603, Manufacturer=Kemet, Supplier Part Number 1=399-5348-1-ND, TempCo=X7R, Tolerance_%=10%, Value1=Unknown, Value2=50V, ValueDisplayed=1000pF
C14: library part CMP-0007434-4, "CAP, CERM, 0.1 uF, 50 V, +/- 10%, X7R, 0603", Cap_Case=0603, Manufacturer=MuRata, Supplier Part Number 1=490-1519-1-ND, TempCo=X7R, Tolerance_%=10%, Value1=Unknown, Value2=50V, ValueDisplayed=0.1uF
C15: library part CMP-0006989-1, "CAP, CERM, 100 pF, 50 V, +/- 5%, C0G/NP0, 0603", Cap_Case=0603, Manufacturer=TDK, Supplier Part Number 1=445-173611-1-ND, TempCo=C0G/NP0, Tolerance_%=5%, Value1=Unknown, Value2=50V, ValueDisplayed=100pF
C16: library part CMP-0007170-4, "CAP, CERM, 10 pF, 50 V, +/- 5%, C0G/NP0, 0603", Cap_Case=0603, Manufacturer=MuRata, Supplier Part Number 1=490-1403-1-ND, TempCo=C0G/NP0, Tolerance_%=5%, Value1=Unknown, Value2=50V, ValueDisplayed=10pF
C17: library part CMP-0007020-3, "CAP, CERM, 2.2 uF, 35 V, +/- 10%, X5R, 0603", Cap_Case=0603, Manufacturer=TDK, Supplier Part Number 1=445-8025-1-ND, TempCo=X5R, Tolerance_%=10%, Value1="0.007674 ohm", Value2=35V, ValueDisplayed=DNP
C18: library part CMP-0007885-2, "CAP, CERM, 4.7 uF, 35 V, +/- 10%, X7R, 0805", Cap_Case=0805, Manufacturer=TDK, Supplier Part Number 1=445-7555-1-ND, TempCo=X7R, Tolerance_%=10%, Value1="0.002346 ohm", Value2=35V, ValueDisplayed=4.7uF
C19: library part CMP-0007857-1, "CAP, CERM, 2.2 uF, 50 V, +/- 10%, X6S, 0805", Cap_Case=0805, Manufacturer=TDK, Supplier Part Number 1=445-7597-1-ND, TempCo=X6S, Tolerance_%=10%, Value1="0.00366 ohm", Value2=50V, ValueDisplayed=2.2uF
C20: library part CMP-0086153-1, "CAP, CERM, 10 µF, 50 V,+/- 10%, X5R, 1206", Cap_Case=1206, Manufacturer="Taiyo Yuden", TempCo=X5R, Tolerance_%=10%, Value2=50V, ValueDisplayed=10µF
C21: library part CMP-0006297-2, "CAP, CERM, 0.1 uF, 50 V, +/- 10%, X7R, 0402", Cap_Case=0402, Manufacturer=TDK, Supplier Part Number 1=445-5932-1-ND, TempCo=X7R, Tolerance_%=10%, Value1="0.039064 ohm", Value2=50V, ValueDisplayed=0.1uF
C22: library part CMP-0008959-2, "CAP, CERM, 22 uF, 10 V, +/- 10%, X7R, 1206", Cap_Case=1206, Manufacturer=MuRata, Supplier Part Number 1=490-5309-1-ND, TempCo=X7R, Tolerance_%=10%, Value1=Unknown, Value2=10V, ValueDisplayed=22uF
C23: library part CMP-0006533-1, "CAP, CERM, 10 uF, 6.3 V, +/- 20%, X5R, 0402", Cap_Case=0402, Manufacturer=MuRata, TempCo=X5R, Tolerance_%=20%, Value1=Unknown, Value2=6.3V, ValueDisplayed=10uF
C24: library part CMP-0088531-2, "0.1µF ±10% 6.3V Ceramic Capacitor X5R 0201 (0603 Metric)", Digikey Part Number=490-3167-1-ND, Manufacturer=Murata, Mouser Part Number=81-GRM033R60J104KE19, Operating Temperature Range="-55°C to +85°C", TempCo=15%, Temperature Characteristic=X5R, Tolerance_%=10%, ValueDisplayed=0.1uF, Voltage=6.3V
C25: library part CMP-0009702-2, "CAP, CERM, 0.47 uF, 6.3 V, +/- 10%, X5R, 0201", Cap_Case=0201, Manufacturer=MuRata, Supplier Part Number 1=490-10409-1-ND, TempCo=X5R, Tolerance_%=10%, Value1=Unknown, Value2=6.3V, ValueDisplayed=0.47uF
C26: library part CMP-0007380-4, "CAP, CERM, 1 uF, 16 V, +/- 10%, X7R, 0603", Cap_Case=0603, Manufacturer=MuRata, Supplier Part Number 1=490-10734-1-ND, TempCo=X7R, Tolerance_%=10%, Value1=Unknown, Value2=16V, ValueDisplayed=1uF
C27: library part CMP-0006532-2, "CAP, CERM, 1 uF, 6.3 V, +/- 10%, X5R, 0402", Cap_Case=0402, Manufacturer=MuRata, Supplier Part Number 1=490-1320-1-ND, TempCo=X5R, Tolerance_%=10%, Value1=Unknown, Value2=6.3V, ValueDisplayed=1uF
C28: library part CMP-0007506-5, "CAP, CERM, 2.2 uF, 10 V, +/- 10%, X5R, 0603", Cap_Case=0603, Manufacturer="Taiyo Yuden", Supplier Part Number 1=587-1253-1-ND, TempCo=X5R, Tolerance_%=10%, Value1=Unknown, Value2=10V, ValueDisplayed=2.2uF
C29: library part CMP-0006298-2, "CAP, CERM, 0.047 uF, 50 V, +/- 10%, X7R, 0402", Cap_Case=0402, Manufacturer=TDK, Supplier Part Number 1=445-7336-1-ND, TempCo=X7R, Tolerance_%=10%, Value1="0.06407 ohm", Value2=50V, ValueDisplayed=0.047uF
C30: library part CMP-0006354-2, "CAP, CERM, 1000 pF, 50 V, +/- 10%, X7R, AEC-Q200 Grade 1, 0402", Cap_Case=0402, Manufacturer=MuRata, Supplier Part Number 1=490-4761-1-ND, TempCo=X7R, Tolerance_%=10%, Value1=Unknown, Value2=50V, ValueDisplayed=1000pF
C31: library part CMP-0008959-2, "CAP, CERM, 22 uF, 10 V, +/- 10%, X7R, 1206", Cap_Case=1206, Manufacturer=MuRata, Supplier Part Number 1=490-5309-1-ND, TempCo=X7R, Tolerance_%=10%, Value1=Unknown, Value2=10V, ValueDisplayed=0.1uF
C32: library part CMP-0080734-1, "CAP, CERM, 470 pF, 10 V,+/- 5%, C0G/NP0, 0603", Cap_Case=0603, Manufacturer="Wurth Elektronik", Supplier Part Number 1=732-7756-1-ND, TempCo=C0G/NP0, Tolerance_%=5%, Value2=10V, ValueDisplayed=470pF
D1: library part CMP-0029209-3, "Diode, Switching-Bridge, 600 V, 1.5 A, DF-S", Manufacturer="Diodes Inc.", Value1=1.5A, Value2=1.1V
D2: library part CMP-0005708-3, "Diode, TVS, Uni, 150 V, 243 Vc, SMC", Manufacturer="Micro Commercial Components", Value1=1500W
D3 D4: library part CMP-0076945-2, "Diode, P-N, 600 V, 1 A, MINI-SMA", Manufacturer="Comchip Technology", Value1=1A, Value2=1.1V
D5: library part CMP-0029033-2, "Diode, Ultrafast, 600 V, 1 A, AEC-Q101, SMA", Manufacturer="ON Semiconductor", Value1=1A, Value2=1.05V
D6: library part CMP-0079155-3, "Diode, Ultrafast, 200 V, 8 A, DPAK", Manufacturer=STMicroelectronics, Value1=8A, Value2=1.05V
D7 D9 D11: library part CMP-0029150-1, "Diode, Switching, 200 V, 0.2 A, AEC-Q101, SOD-323", Manufacturer="ON Semiconductor", Supplier Part Number 1=BAS20HT1GOSCT-ND, Value1=0.2A, Value2=1.25V
D8: library part CMP-0077615-3, "Diode, Zener, 18 V, 500 mW, SOD-123", Manufacturer=Vishay-Semiconductor, Power_W=500mW, Value1=0.5W
D14: library part CMP-0002947-3, "LED, Red, SMD", Color=Red, Manufacturer="Wurth Elektronik", Power_TotalModule=72mW, Value1=0.072W, Value2=2V
F1: library part CMP-0003561-2, "Fuse, 3.15 A, 250VAC/VDC, TH", Irating_A=3.15A, Manufacturer=Littelfuse, Supplier Part Number 1=F5504CT-ND
J2: library part CMP-0054796-2, "Header, 2.54 mm, 3x1, Gold, TH", Color=Black, Manufacturer="Wurth Elektronik", Supplier Part Number 1=732-5316-ND
J4: library part CMP-0054798-2, "Header, 2.54 mm, 4x1, Gold, TH", Color=Black, Manufacturer="Wurth Elektronik", Supplier Part Number 1=732-5317-ND
L1: library part CMP-0076855-1, "Coupled inductor, 1.8 mH, 1 A, 0.31 ohm, TH", Manufacturer="Wurth Elektronik", Supplier Part Number 1=732-4224-5-ND, ValueDisplayed=1.8mH
L2: library part CMP-0079596-1, "Inductor, Wirewound, 1 mH, 0.8 A, 0.75 ohm, TH", Manufacturer="Wurth Elektronik", Supplier Part Number 1=732-7182-ND, Value1="0.75 ohm", Value2=0.8A, ValueDisplayed=1mH
L3: library part CMP-0064683-2, "Inductor, Shielded, Powdered Iron, 47 uH, 0.39 A, 2.3 ohm, AEC-Q200 Grade 1, SMD", Manufacturer="Wurth Elektronik", Supplier Part Number 1=732-6947-1-ND, Value1="2.3 ohm", Value2=0.39A, ValueDisplayed=47uH
LOGO1: library part CMP-0074835-1, "IEC 61010-1 High Voltage Warning"
LOGO2: library part CMP-0074837-1, "IEC 61010-1 Hot Surface Warning"
Logo3: library part CMP-0074844-1
Logo4: library part CMP-0074838-1, "Texas Instrument Corporate Signature"
Logo5: library part CMP-0074847-1, "FCC_disclaimer"
Logo6: library part CMP-0074769-1
MOV1: library part CMP-0092775-1, "470 V 6.5 kA Varistor 1 Circuit Through Hole Disc 20mm", Clamping Voltage=775V, Digikey Part Number=MOV-20D471K-ND, Manufacturer="Bourns Inc.", Mouser Part Number=652-MOV-20D471K, Operating Temperature Range="-40°C to +105°C", ValueDisplayed=1020pF, Varistor Voltage=423V, Voltage Tolerance=10%
Q1: library part CMP-0081521-2, "MOSFET, N-CH, 700 V, 12.5 A, DPAK", Alternate Manufacturer=None, Manufacturer="Infineon Technologies", Supplier Part Number 1=IPD70R360P7SAUMA1CT-ND, Value1="? ohm", Value2="16.4 nC"
Q2: library part CMP-0000387-2, "Transistor, NPN, 40 V, 0.2 A, SOT-23", Manufacturer="Diodes Inc.", Supplier Part Number 1=MMBT3904-FDICT-ND, Value1="0.2 A", Value2=400
Q3: library part CMP-0000326-2, "Transistor, PNP, 40 V, 0.2 A, SOT-23", Manufacturer="Diodes Inc.", Supplier Part Number 1=MMBT3906-FDICT-ND, Value1="0.2 A", Value2=400
R1 R4: library part CMP-0083494-1, "RES, 200 k, 5%, 0.5 W, 1210", Manufacturer=Yageo, Power_W=500mW, TempCo="100 ppm/C", Tolerance_%=5%, Value2=0.5W, Value_Code=200k
R2: library part CMP-0015919-3, "RES, 22, 5%, 1.5 W, AEC-Q200 Grade 0, 2512", Manufacturer=Vishay-Dale, Power_W=1.5W, TempCo="200 ppm/C", Tolerance_%=5%, Value_Code=22R0, ValueDisplayed=22
R3: library part CMP-0018687-3, "RES, 47, 5%, 0.25 W, AEC-Q200 Grade 0, 1206", Manufacturer=Vishay-Dale, Power_W=250mW, Supplier Part Number 1=541-47ECT-ND, TempCo="200 ppm/C", Tolerance_%=5%, Value2=0.25W, Value_Code=47R0, ValueDisplayed=47
R5 R10: library part CMP-0018353-2, "RES, 510 k, 1%, 0.25 W, 1206", Manufacturer="Yageo America", Power_W=250mW, Supplier Part Number 1=311-510KFRCT-ND, TempCo="100 ppm/C", Tolerance_%=1%, Value2=0.25W, Value_Code=510k
R6: library part CMP-0020817-2, "RES, 3.3, 5%, 0.125 W, 0805", Manufacturer="Yageo America", Power_W=125mW, Supplier Part Number 1=311-3.3ARCT-ND, TempCo="200 ppm/C", Tolerance_%=5%, Value2=0.125W, Value_Code=3R30, ValueDisplayed=3.3
R7: library part CMP-0023014-4, "RES, 301 k, 1%, 0.1 W, 0603", Manufacturer=Yageo, Power_W=100mW, Supplier Part Number 1=311-301KHRCT-ND, TempCo="100 ppm/C", Tolerance_%=1%, Value2=0.1W, Value_Code=301k
R8: library part CMP-0023018-5, "RES, 30.1 k, 1%, 0.1 W, 0603", Manufacturer=Yageo, Power_W=100mW, Supplier Part Number 1=311-30.1KHRCT-ND, TempCo="100 ppm/C", Tolerance_%=1%, Value2=0.1W, Value_Code=30k1, ValueDisplayed=30.1k
R9: library part CMP-0023133-5, "RES, 47.0 k, 1%, 0.1 W, 0603", Manufacturer=Yageo, Power_W=100mW, Supplier Part Number 1=311-47.0KHRCT-ND, TempCo="100 ppm/C", Tolerance_%=1%, Value2=0.1W, Value_Code=47k0, ValueDisplayed=47.0k
R11: library part CMP-0020812-2, "RES, 2.2, 5%, 0.125 W, 0805", Manufacturer="Yageo America", Power_W=125mW, Supplier Part Number 1=311-2.2ARCT-ND, TempCo="200 ppm/C", Tolerance_%=5%, Value2=0.125W, Value_Code=2R20, ValueDisplayed=2.2
R12: library part CMP-0020832-2, "RES, 4.7, 5%, 0.25 W, 0805", Manufacturer="Stackpole Electronics Inc", Power_W=250mW, Supplier Part Number 1=RPC0805JT4R70CT-ND, TempCo="200 ppm/C", Tolerance_%=5%, Value2=0.25W, Value_Code=4R70, ValueDisplayed=4.7
R13: library part CMP-0023253-5, "RES, 6.80 k, 1%, 0.1 W, 0603", Manufacturer=Yageo, Power_W=100mW, Supplier Part Number 1=311-6.80KHRCT-ND, TempCo="100 ppm/C", Tolerance_%=1%, Value2=0.1W, Value_Code=6k80, ValueDisplayed=6.80k
R14: library part CMP-0025696-3, "RES, 4.7 k, 5%, 0.1 W, 0603", Manufacturer=Bourns, Power_W=100mW, Supplier Part Number 1=CR0603-JW-472GLFCT-ND, TempCo="200 ppm/C", Tolerance_%=5%, Value2=0.1W, Value_Code=4k70, ValueDisplayed=2.47k
R15 R19: library part CMP-0025899-5, "RES, 1.0 k, 5%, 0.1 W, 0603", Manufacturer=Yageo, Power_W=100mW, Supplier Part Number 1=311-1.0KGRCT-ND, TempCo="100 ppm/C", Tolerance_%=5%, Value2=0.1W, Value_Code=1k00, ValueDisplayed=1.0k
R16: library part CMP-0023100-4, "RES, 412 k, 1%, 0.1 W, 0603", Manufacturer=Yageo, Power_W=100mW, Supplier Part Number 1=311-412KHRCT-ND, TempCo="100 ppm/C", Tolerance_%=1%, Value2=0.1W, Value_Code=412k
R17: library part CMP-0016021-2, "RES, 0.68, 5%, 1 W, 2512", Manufacturer=Panasonic, Power_W=1W, Supplier Part Number 1=PT.68UCT-ND, TempCo="200 ppm/C", Tolerance_%=5%, Value_Code=R680, ValueDisplayed=0.68
R18: library part CMP-0026658-1, "RES, 10.0 k, 1%, 0.1 W, 0402", Manufacturer=Panasonic, Power_W=100mW, Supplier Part Number 1=P10.0KLCT-ND, TempCo="100 ppm/C", Tolerance_%=1%, Value2=0.1W, Value_Code=10k0, ValueDisplayed=10.0k
R20: library part CMP-0026996-2, "RES, 20 k, 5%, 0.1 W, AEC-Q200 Grade 0, 0402", Manufacturer=Panasonic, Power_W=100mW, Supplier Part Number 1=P20KJCT-ND, TempCo="200 ppm/C", Tolerance_%=5%, Value2=0.1W, Value_Code=20k0, ValueDisplayed=20k
R21: library part CMP-0022852-5, "RES, 18.0 k, 1%, 0.1 W, 0603", Manufacturer=Yageo, Power_W=100mW, Supplier Part Number 1=311-18.0KHRCT-ND, TempCo="100 ppm/C", Tolerance_%=1%, Value2=0.1W, Value_Code=18k0, ValueDisplayed=18.0k
R22: library part CMP-0026740-1, "RES, 4.99 k, 1%, 0.063 W, 0402", Manufacturer="Yageo America", Power_W=63mW, Supplier Part Number 1=311-4.99KLRCT-ND, TempCo="100 ppm/C", Tolerance_%=1%, Value2=0.063W, Value_Code=4k99, ValueDisplayed=4.99k
R23: library part CMP-0023132-5, "RES, 47.5 k, 1%, 0.1 W, 0603", Manufacturer=Yageo, Power_W=100mW, Supplier Part Number 1=311-47.5KHRCT-ND, TempCo="100 ppm/C", Tolerance_%=1%, Value2=0.1W, Value_Code=47k5, ValueDisplayed=47.5k
R24: library part CMP-0026737-1, "RES, 47.0 k, 1%, 0.0625 W, 0402", Manufacturer="Yageo America", Power_W=62.5mW, Supplier Part Number 1=311-47.0KLRCT-ND, TempCo="100 ppm/C", Tolerance_%=1%, Value2=0.0625W, Value_Code=47k0, ValueDisplayed=47.0k
R25 R35: library part CMP-0026825-1, "RES, 10 k, 5%, 0.063 W, 0402", Manufacturer=Vishay-Dale, Power_W=63mW, Supplier Part Number 1=541-10KJCT-ND, TempCo="200 ppm/C", Tolerance_%=5%, Value2=0.063W, Value_Code=10k0, ValueDisplayed=10k
R26 R27 R34: library part CMP-0023198-5, "RES, 5.10 k, 1%, 0.1 W, 0603", Manufacturer=Yageo, Power_W=100mW, Supplier Part Number 1=311-5.10KHRCT-ND, TempCo="100 ppm/C", Tolerance_%=1%, Value2=0.1W, Value_Code=5k10, ValueDisplayed=5.10k
R28 R30 R31 R32: library part CMP-0026849-3, "RES, 180, 5%, 0.063 W, AEC-Q200 Grade 0, 0402", Manufacturer=Vishay-Dale, Power_W=63mW, Supplier Part Number 1=541-180JCT-ND, TempCo="200 ppm/C", Tolerance_%=5%, Value2=0.063W, Value_Code=180R, ValueDisplayed=180
R29: library part CMP-0025830-4, "RES, 5.1 k, 5%, 0.1 W, AEC-Q200 Grade 0, 0603", Manufacturer=Vishay-Dale, Power_W=100mW, Supplier Part Number 1=541-5.1KGCT-ND, TempCo="200 ppm/C", Tolerance_%=5%, Value2=0.1W, Value_Code=5k10, ValueDisplayed=0
R33: library part CMP-0015865-2, "RES, 0, 5%, 1.5 W, AEC-Q200 Grade 0, 2512", Manufacturer=Vishay-Dale, Power_W=1.5W, Supplier Part Number 1=541-0.0RBCT-ND, TempCo=ppm/C, Tolerance_%=5%, Value_Code=0000, ValueDisplayed=0
R36: library part CMP-0078659-1, "RES, 1.00 k, 0.5%, 0.063 W, AEC-Q200 Grade 0, 0402", Manufacturer=Panasonic, Power_W=63mW, Supplier Part Number 1=P1.0KDECT-ND, TempCo="25 ppm/C", Tolerance_%=0.5%, Value2=0.063W, Value_Code=1k00, ValueDisplayed=1.00k
RT1: library part CMP-0078760-1, "Thermistor NTC, 5 ohm, 20%, D20xT6mm", Manufacturer=TKS, Power_W=4.9W, Tolerance_%=20%
T1: library part CMP-0098488-1, "FLYBACK TRANSFORMER", Manufacturer="GCI Technologies", Operating Temperature Range=to, Voltage_Isolation_Vrms=3kV
U1: library part CMP-0029884-1, "LED Lighting Power Controller, -40 to +105 degC, 8-pin SOIC (D), Green (RoHS & no Sb/Br)", Frequency(Max)(kHz)=200, Manufacturer="Texas Instruments", Rating=Catalog
U2: library part CMP-0006163-3, "Optocoupler, 3.75 kV, 80-160% CTR, SMT", Manufacturer=Vishay-Semiconductor, Supplier Part Number 1=VOS617A-7X001T-ND, Voltage_Isolation_Vrms=3.75kV
U3: library part CMP-0066199-1, "2.5V Low Iq Adjustable Precision Shunt Regulator, DBZ0003A (SOT-23-3)", Alternate Manufacturer="Texas Instruments"
U4: library part CMP-0097009-1, "Sensorless Field Oriented Control (FOC) Integrated FET BLDC Driver VQFN40", Manufacturer="Texas Instruments", Max Supply Voltage=35V, Min Supply Voltage=4.5V, Nominal Supply Current=11-28mA, Operating Temperature Range="-40°C to +150°C", Switching Frequency=75kHz
U5: library part CMP-0093964-1, "Mixed-Signal Microcontrollers", Frequency_Fixed=32MHz, Manufacturer="Texas Instruments", Max Supply Voltage=3.6V, Min Supply Voltage=1.62V, Operating Temperature Range="-40°C to +125°C"
U6: library part CMP-0087036-1, "IR RECEIVER, 35M, 950NM, SIP", Manufacturer="Vishay Semiconductor Opto Division"

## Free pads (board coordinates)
  round 94.49 hole 94.49: 1(440.77,2270.28) 1(1778.83,293.94)
  round 118.11 hole 118.11: 1(502.21,1583.93) 1(1164.38,605.92) 1(2525.69,2244.12)
  oval 118.11x78.74 hole 51.18: 2(324.8,2442.91) 3(187.92,2052.57)

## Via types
v1: diameter 20, hole 10, Top Layer to Bottom Layer, tented both sides, 70 vias
v2: diameter 20, hole 10, Top Layer to Bottom Layer, 51 vias
v3: diameter 24, hole 8, Top Layer to Bottom Layer, tented both sides, 45 vias

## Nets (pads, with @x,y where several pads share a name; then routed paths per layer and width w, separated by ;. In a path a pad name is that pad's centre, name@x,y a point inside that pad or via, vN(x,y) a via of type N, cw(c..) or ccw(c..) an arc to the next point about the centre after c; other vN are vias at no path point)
+24V: 24V.1 C4.2 C5.1 C6.1 C7.1 C8.1 D6.2 R14.2 R16.2 R33.1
